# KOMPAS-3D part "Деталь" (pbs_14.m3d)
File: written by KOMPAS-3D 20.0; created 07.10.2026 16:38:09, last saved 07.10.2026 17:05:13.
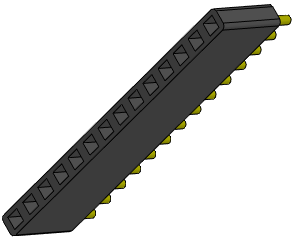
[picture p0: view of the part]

Document properties: Полное имя файла: D:\myProjects\Progect_esp32\box_compas\разъемы\pbs_14.m3d

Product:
- Part/product: Деталь
    Масса: 0.00427494
  - Body: Тело 1
      Масса: 0.00428927

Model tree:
1. Эскиз:1
2. Элемент выдавливания:1
     Расстояние 1 = 8.5
3. Эскиз:2  (with: Элемент выдавливания:1)
4. Элемент выдавливания:2
     Расстояние 1 = 3
5. Массив по сетке:2  (with: Элемент выдавливания:2, Эскиз:2)  (14 pattern instances)
     Шаг 1 = 2.54; Угол раствора = 90
6. Эскиз:3  (with: Элемент выдавливания:1)
7. Элемент выдавливания:3
     Расстояние 2 = 8
8. Массив по сетке:3  (with: Элемент выдавливания:3, Эскиз:3)  (14 pattern instances)
     Шаг 1 = 2.54; Угол раствора = 90; Геометрический массив = 128
9. Скругление:1  (with: Элемент выдавливания:1)
     Радиус = 0.5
